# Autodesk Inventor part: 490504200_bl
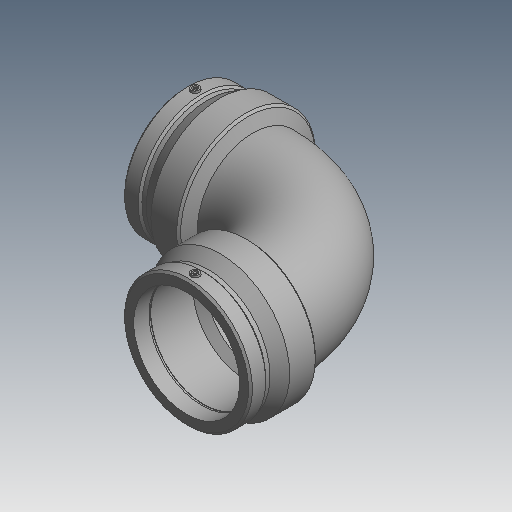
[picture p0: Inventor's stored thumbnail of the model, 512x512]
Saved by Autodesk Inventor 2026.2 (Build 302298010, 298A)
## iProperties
Created: 2017-06
Part Number: 490504200_bl
Material: Generic
Description: PLASSON 90° ELBOW 200
Document SubType Name: Modeling
Designer: KIM
Mass: 55.0731 g
Surface Area: 148.067 cm^2
Volume: 55.0731 cm^3
Density: 1 g/cm^3
Appearance: Default
Author: KIM
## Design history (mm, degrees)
derived "490504.ipt"
feature "Solid1::490504.ipt" dims "ScaleForDerivedMember" = 10
tag "TaggingFeature1"
body "Solid1"
other parameters: "d2" = 262 [user parameter], "d4" = 112.25 [user parameter], "d5" = 235.8 [user parameter], "d8" = 168 deg [user parameter], "d10" = 44.8 [user parameter], "d11" = 14.93333 [user parameter], "d14" = 17.6296 [user parameter], "d19" = 3.52592 [user parameter], "d20" = 168 deg [user parameter], "d22" = 241.04 [user parameter], "d23" = 262 [user parameter], "d24" = 233.8088 [user parameter], "d29" = 124 [user parameter], "d30" = 15 [user parameter], "d31" = 157.15 [user parameter], "d34" = 5 deg [user parameter], "d35" = 15 [user parameter], "d39" = 5 deg [user parameter], "d41" = 4 [user parameter], "d42" = 14 [user parameter], "d43" = 0 [user parameter], "d45" = 4 [user parameter], "d46" = 14 [user parameter], "d47" = 0 [user parameter], "d51" = 44.8 [user parameter], "d52" = 112 [user parameter], "d54" = 90 deg [user parameter], "d67" = 45 deg [user parameter], "d71" = 90 deg [user parameter], "d75" = 13.1 [user parameter], "d82" = 45 deg [user parameter], "d83" = 112 [user parameter], "d84" = 235.8 [user parameter], "d87" = 90 deg [user parameter], "d90" = 112 [user parameter], "d91" = 0 [user parameter], "d92" = 112 [user parameter], "d93" = 0 [user parameter], "d94" = 90 deg [user parameter], "d101" = 3 [user parameter], "d102" = 0 [user parameter], "d103" = 3 [user parameter], "d104" = 0 [user parameter], "d105" = 32.48 [user parameter], "d106" = 8.12 [user parameter], "d110" = 61.6 [user parameter], "d111" = 449 [user parameter], "d112" = 449 [user parameter], "d113" = 449 [user parameter], "d114" = 449 [user parameter], "L_" = 449 [user parameter], "L_1" = 112 [user parameter], "D_" = 262 [user parameter], "A_" = 124 [user parameter], "d_2" = 12 [user parameter]
